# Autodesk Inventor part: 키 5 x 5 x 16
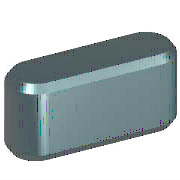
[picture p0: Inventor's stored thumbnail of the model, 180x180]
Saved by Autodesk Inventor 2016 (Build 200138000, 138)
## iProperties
IsCustomPart: 1
Created: 2012-02
Part Number: 키 5 x 5 x 16
Material: 강철, 연강
Description: 키 및 해당 키홈
Document SubType Name: Modeling
Standard: KS B 1311
Designer: mduedu
Standards Organization: KS
Language: ko-KR
Size Designation: 5 x 5 x 16
Categories: <MemberInstance><Categories><Category DisplayName="샤프트 부품" InternalName="7f7aeb1f-a693-4053-b835-cee3144e0d98" Mnemonic="SHFT"><Category DisplayName="키" Interna
Density: 1 g/cm^3
Appearance: 강철
Author: mduedu
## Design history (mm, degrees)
workplane "Work Plane1"
workplane "Work Plane2"
sketch "스케치1"
  geometry: L1 (2.5, 2.5)-(13.5, 2.5); L2 (13.5, -2.5)-(2.5, -2.5); L3 (0, 9.4)-(0, -7.4) reference; L4 (-5, 0)-(30, 0) reference; L5 (16, 0)-(16, 7); A1 r 2.5 centre (2.5, 0) between (2.5, 2.5) and (2.5, -2.5); A2 r 2.5 centre (13.5, 0) between (13.5, -2.5) and (13.5, 2.5)
  constraints: 6 end point, 5 point on circle, 4 tangent, 3 point on line, 2 centre point, 1 horizontal, 1 parallel, 1 perpendicular
  dimensions: "d0" = 2.5 radius of A1 (= 0.5 x PB); "d13" = 2.5 radius of A2 (= 0.5 x PB); "d14" = 16 distance between parallel lines of L5 L3 (= NLG)
extrude "본체1" new body sketch "스케치1" taper "d3" = 0 deg; stored distance "d4" = 10
workplane "Work Plane3"
body "Solid1"
chamfer "모따기1" distance "d8" = 0.4 (= PHH); stored, may be unused: second distance "d9" = 0.4 (= PHH), angle "d15" = 45 deg
other parameters: "d1" = -3 (= -PNT), "d2" = 2 (= PH - PNT), "NLG" = 16 [user parameter; used in 3 equation terms], "PB" = 5 [user parameter; used in 2 equation terms], "PNT" = 3 [user parameter; used in 2 equation terms], "PH" = 5 [user parameter; used in 1 equation term], "PHH" = 0.4 [user parameter; used in 2 equation terms], "d10" = 0, "d16" = 0, "d17" = 0, "d18" = 0, "WDMIN" = 12 [user parameter], "PLB2" = 16 (= NLG) [user parameter], "WDMAX" = 17 [user parameter], "PLB1" = 16 (= NLG) [user parameter], "RR" = 0.16 [user parameter], "PUEB" = 2.3 [user parameter]
